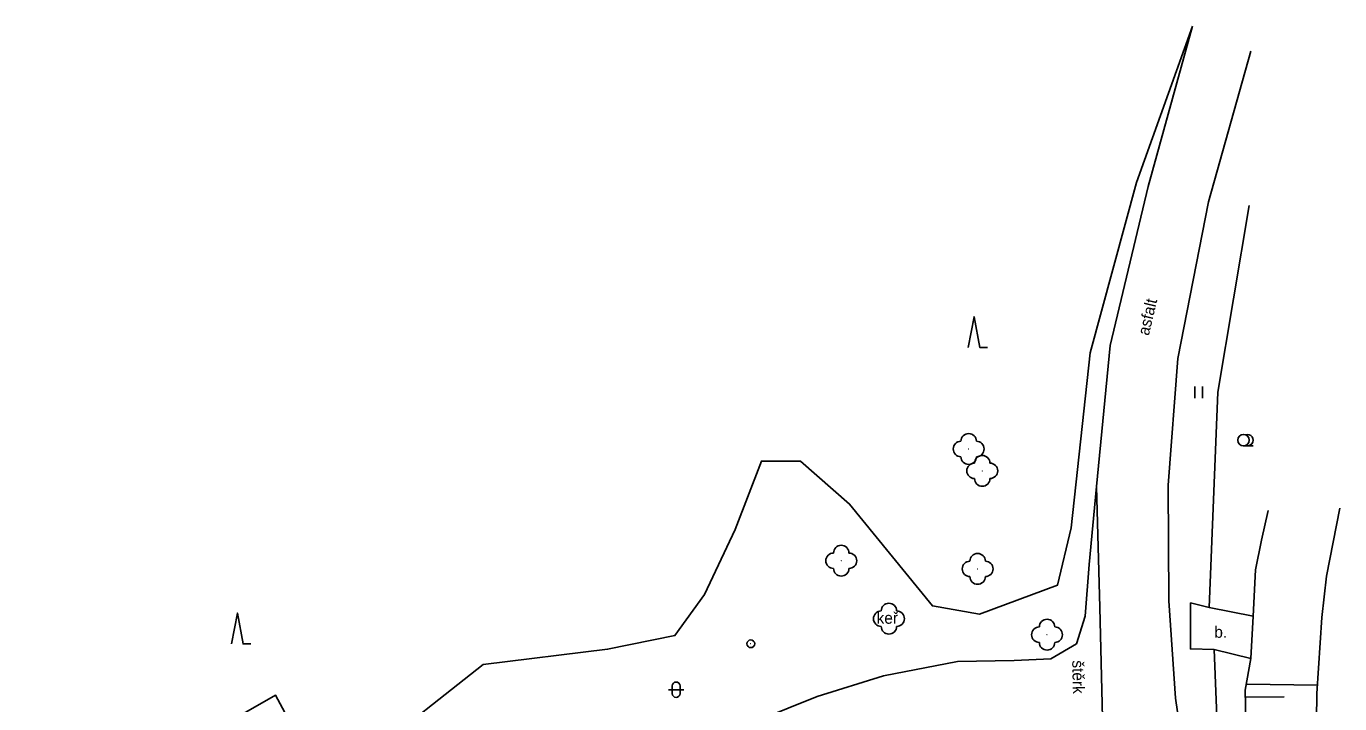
# Model space of a CAD drawing. Extents: x -584400 to -581602, y -1210894 to -1208793.
# Drawn here: x -583100 to -583014.9, y -1209307.4 to -1209263.4 of the extents above; entities that cross this region are included whole.
import ezdxf

# ---------------------------------------------------------------- set-up
doc = ezdxf.new("R2010")
doc.units = 0
for name, color, linetype in [('POMOC_POPIS', 7, 'Continuous'), ('ROZHRANÍ_PLOCH', 7, 'Continuous'), ('VÝŠKOPIS', 7, 'Continuous'), ('ZELEŇ', 7, 'Continuous'), ('ZN_DOPLŇKOVÉ', 7, 'Continuous'), ('ZN_KULTUR', 7, 'Continuous')]:
    doc.layers.add(name, color=color, linetype=linetype)

msp = doc.modelspace()

# ---------------------------------------------------------------- linework, layer by layer
at = {"layer": 'ROZHRANÍ_PLOCH'}
for points in [[(-583024.43, -1209263.45), (-583027.3, -1209273.84), (-583029.76, -1209284.16), (-583030.65, -1209293.31)], [(-583024.38, -1209314.88), (-583025.54, -1209307.04), (-583025.97, -1209300.74), (-583026.02, -1209293.23), (-583025.39, -1209285), (-583023.4, -1209274.85), (-583020.65, -1209265.06)], [(-583030.65, -1209293.31), (-583031.14, -1209298.37), (-583031.4, -1209301.73), (-583031.95, -1209303.52), (-583033.62, -1209304.49), (-583035.99, -1209304.6), (-583039.66, -1209304.66), (-583044.46, -1209305.59), (-583048.76, -1209306.95), (-583054.41, -1209309.21)], [(-583030.65, -1209293.31), (-583030.43, -1209301.16), (-583030.27, -1209308.32), (-583031.59, -1209308.69)], [(-583023.02, -1209303.89), (-583024.57, -1209303.85), (-583024.56, -1209300.87), (-583023.35, -1209301.17)], [(-583023.35, -1209301.17), (-583020.49, -1209301.72)], [(-583020.65, -1209304.48), (-583023.02, -1209303.89)]]:
    msp.add_lwpolyline(points, dxfattribs=at)
at = {"layer": 'VÝŠKOPIS'}
for points in [[(-583014.89, -1209294.71), (-583015.74, -1209299.14), (-583016.05, -1209301.82), (-583016.37, -1209306.75), (-583016.47, -1209313.52), (-583016.51, -1209317.37), (-583016.55, -1209321.51), (-583016.68, -1209323.06), (-583017.21, -1209327.13)], [(-583019.53, -1209294.88), (-583019.97, -1209296.79), (-583020.34, -1209298.72), (-583020.49, -1209301.72)], [(-583020.49, -1209301.72), (-583020.65, -1209304.48)], [(-583020.65, -1209304.48), (-583021.01, -1209306.53), (-583020.98, -1209308.49), (-583020.89, -1209310.07), (-583020.73, -1209312.03), (-583020.65, -1209314), (-583020.65, -1209315.97), (-583020.72, -1209317.93), (-583020.88, -1209319.89), (-583021.12, -1209321.85), (-583021.44, -1209323.79), (-583021.83, -1209325.71), (-583022.22, -1209327.31)], [(-583016.33, -1209306.2), (-583020.94, -1209306.14)], [(-583018.5, -1209306.97), (-583021, -1209306.98)]]:
    msp.add_lwpolyline(points, dxfattribs=at)
at = {"layer": 'ZELEŇ'}
for points in [[(-583109.08, -1209326.02), (-583099.42, -1209319.06), (-583097.31, -1209319.15), (-583093.39, -1209317.04), (-583090.55, -1209313.61), (-583090.43, -1209310.61), (-583083.86, -1209306.86), (-583081.88, -1209310.55), (-583077.91, -1209310.8), (-583070.4, -1209304.86), (-583062.35, -1209303.87), (-583057.98, -1209302.99), (-583056.06, -1209300.32), (-583054.08, -1209296.1), (-583052.37, -1209291.67), (-583049.84, -1209291.67), (-583046.66, -1209294.46), (-583041.29, -1209301.06), (-583038.23, -1209301.6), (-583033.19, -1209299.72), (-583032.29, -1209296), (-583031.07, -1209284.64), (-583028.06, -1209273.59), (-583024.43, -1209263.45)], [(-583023.35, -1209301.17), (-583022.8, -1209287.2), (-583020.77, -1209275.08)], [(-583023.02, -1209303.89), (-583022.2, -1209324.58)]]:
    msp.add_lwpolyline(points, dxfattribs=at)
for centre in [(-583038.94, -1209290.88), (-583038.06, -1209292.3), (-583047.2, -1209298.13), (-583038.36, -1209298.66), (-583044.11, -1209301.89), (-583033.86, -1209302.93)]:
    msp.add_circle(centre, 0.0005, dxfattribs=at)
for centre, start, end in [((-583039.44, -1209290.88), 89.99999, 269.99999), ((-583038.94, -1209290.38), 0, 179.99999), ((-583038.44, -1209290.88), 270, 89.99999), ((-583038.94, -1209291.38), 179.99999, 359.99999), ((-583038.06, -1209291.8), 0, 179.99999), ((-583038.56, -1209292.3), 89.99999, 269.99999), ((-583037.56, -1209292.3), 270, 89.99999), ((-583038.06, -1209292.8), 179.99999, 359.99999), ((-583047.2, -1209297.63), 0, 179.99999), ((-583047.7, -1209298.13), 89.99999, 269.99999), ((-583046.7, -1209298.13), 270, 89.99999), ((-583038.86, -1209298.66), 89.99999, 269.99999), ((-583038.36, -1209298.16), 0, 179.99999), ((-583037.86, -1209298.66), 270, 89.99999), ((-583047.2, -1209298.63), 179.99999, 359.99999), ((-583038.36, -1209299.16), 179.99999, 359.99999), ((-583044.61, -1209301.89), 89.99999, 269.99999), ((-583044.11, -1209301.39), 0, 179.99999), ((-583043.61, -1209301.89), 270, 89.99999), ((-583044.11, -1209302.39), 179.99999, 359.99999), ((-583034.36, -1209302.93), 89.99999, 269.99999), ((-583033.86, -1209302.43), 0, 179.99999), ((-583033.36, -1209302.93), 270, 89.99999), ((-583033.86, -1209303.43), 179.99999, 359.99999)]:
    msp.add_arc(centre, 0.5, start, end, dxfattribs=at)
at = {"layer": 'ZN_DOPLŇKOVÉ'}
for radius in [0.25, 0.0005]:
    msp.add_circle((-583053.061, -1209303.52), radius, dxfattribs=at)
at = {"layer": 'ZN_KULTUR'}
for p, q in [((-583024.28, -1209287.575), (-583024.28, -1209286.825)), ((-583023.78, -1209287.575), (-583023.78, -1209286.825)), ((-583021.13, -1209290.685), (-583020.505, -1209290.685)), ((-583058.4, -1209306.5), (-583057.4, -1209306.5)), ((-583058.15, -1209306.75), (-583058.15, -1209306.25)), ((-583057.65, -1209306.75), (-583057.65, -1209306.25))]:
    msp.add_line(p, q, dxfattribs=at)
for points in [[(-583038.965, -1209284.3), (-583038.59, -1209282.3), (-583038.215, -1209284.3), (-583037.715, -1209284.3)], [(-583086.715, -1209303.53), (-583086.34, -1209301.53), (-583085.965, -1209303.53), (-583085.465, -1209303.53)]]:
    msp.add_lwpolyline(points, dxfattribs=at)
msp.add_circle((-583021.13, -1209290.31), 0.375, dxfattribs=at)
for centre, radius, start, end in [((-583020.88, -1209290.31), 0.375, 249.49437, 109.04743), ((-583057.9, -1209306.25), 0.25, 0, 179.99999), ((-583057.9, -1209306.75), 0.25, 179.99999, 359.99999)]:
    msp.add_arc(centre, radius, start, end, dxfattribs=at)

# ---------------------------------------------------------------- texts
at = {"layer": 'POMOC_POPIS'}
for s, rotation, p in [('asfalt', 76.59248, (-583027.27, -1209283.56)), ('štěrk', 271.28016, (-583032.23, -1209304.6))]:
    msp.add_text(s, height=0.75, rotation=rotation, dxfattribs=at).set_placement(p)
msp.add_text('b.', height=0.75, dxfattribs=at).set_placement((-583023.02, -1209303.13))
at = {"layer": 'ZELEŇ'}
msp.add_text('keř', height=0.75, dxfattribs=at).set_placement((-583044.91, -1209302.22))

doc.saveas('drawing.dxf')
